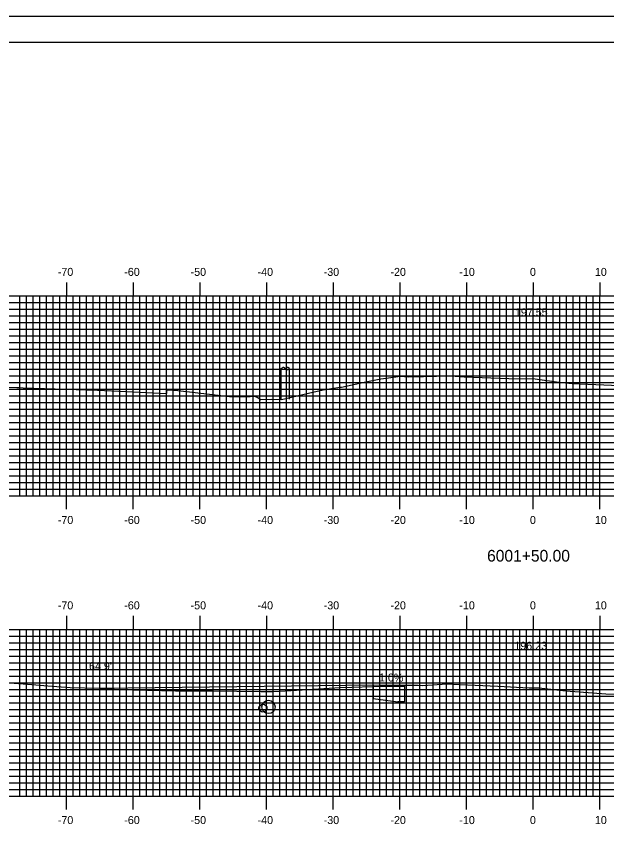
# Model space of a CAD drawing. Extents: x 851300 to 851643, y 366898 to 367118.
# Drawn here: x 851388 to 851476.5, y 366993.9 to 367118.4 of the extents above; entities that cross this region are included whole.
import ezdxf

# ---------------------------------------------------------------- set-up
doc = ezdxf.new("R2010")
doc.units = 0
for name, color, linetype in [('ANNOTATION', 7, 'Continuous'), ('BORDER', 7, 'Continuous'), ('D_Drainage_Culvert', 7, 'Continuous'), ('H_V ANNOTATION', 7, 'Continuous'), ('MAJOR', 7, 'Continuous'), ('MINOR', 7, 'Continuous'), ('PLOT BOUNDARY', 7, 'Continuous'), ('S_Drainage_Invert', 7, 'Continuous'), ('S_Roadway_Centerline', 7, 'Continuous'), ('S_Utilities_Pole_Power', 7, 'Continuous')]:
    doc.layers.add(name, color=color, linetype=linetype)

msp = doc.modelspace()

# ---------------------------------------------------------------- linework, layer by layer
at = {"layer": 'ANNOTATION'}
for p, q in [((851400.61, 367017.65), (851441.5, 367018.16)), ((851441.5, 367018.16), (851441.5, 367016.08)), ((851441.5, 367018.16), (851446.2, 367018.12)), ((851441.5, 367016.08), (851445.2, 367015.62))]:
    msp.add_line(p, q, dxfattribs=at)
for points in [[(851446.2, 367017.87), (851441.5, 367017.91)], [(851446.2, 367018.12), (851446.2, 367015.62), (851445.2, 367015.62)]]:
    msp.add_lwpolyline(points, dxfattribs=at)
at = {"layer": 'BORDER'}
msp.add_lwpolyline([(851315.9, 366904.47), (851635.9, 366904.47), (851635.9, 367114.47), (851315.9, 367114.47)], close=True, dxfattribs=at)
at = {"layer": 'D_Drainage_Culvert'}
msp.add_circle((851425.8, 367014.83), 1, dxfattribs=at)
at = {"layer": 'MAJOR'}
for p, q in [((851395.5, 367078.48), (851395.5, 367076.47)), ((851405.5, 367078.48), (851405.5, 367076.47)), ((851415.5, 367078.48), (851415.5, 367076.47)), ((851425.5, 367078.48), (851425.5, 367076.47)), ((851435.5, 367078.48), (851435.5, 367076.47)), ((851445.5, 367078.48), (851445.5, 367076.47)), ((851455.5, 367078.48), (851455.5, 367076.47)), ((851465.5, 367078.48), (851465.5, 367076.47)), ((851475.5, 367078.48), (851475.5, 367076.47)), ((851325.5, 367076.47), (851605.5, 367076.47)), ((851325.5, 367076.47), (851605.5, 367076.47)), ((851395.5, 367046.47), (851395.5, 367076.47)), ((851405.5, 367046.47), (851405.5, 367076.47)), ((851415.5, 367046.47), (851415.5, 367076.47)), ((851425.5, 367046.47), (851425.5, 367076.47)), ((851435.5, 367046.47), (851435.5, 367076.47)), ((851445.5, 367046.47), (851445.5, 367076.47)), ((851455.5, 367046.47), (851455.5, 367076.47)), ((851465.5, 367046.47), (851465.5, 367076.47)), ((851475.5, 367046.47), (851475.5, 367076.47)), ((851325.5, 367071.47), (851605.5, 367071.47)), ((851325.5, 367066.47), (851605.5, 367066.47)), ((851325.5, 367061.47), (851605.5, 367061.47)), ((851325.5, 367056.47), (851605.5, 367056.47)), ((851325.5, 367051.47), (851605.5, 367051.47)), ((851325.5, 367046.47), (851605.5, 367046.47)), ((851325.5, 367046.47), (851605.5, 367046.47)), ((851395.5, 367044.47), (851395.5, 367046.47)), ((851405.5, 367044.47), (851405.5, 367046.47)), ((851415.5, 367044.47), (851415.5, 367046.47)), ((851425.5, 367044.47), (851425.5, 367046.47)), ((851435.5, 367044.47), (851435.5, 367046.47)), ((851445.5, 367044.47), (851445.5, 367046.47)), ((851455.5, 367044.47), (851455.5, 367046.47)), ((851465.5, 367044.47), (851465.5, 367046.47)), ((851475.5, 367044.47), (851475.5, 367046.47)), ((851395.5, 367028.48), (851395.5, 367026.47)), ((851405.5, 367028.48), (851405.5, 367026.47)), ((851415.5, 367028.48), (851415.5, 367026.47)), ((851425.5, 367028.48), (851425.5, 367026.47)), ((851435.5, 367028.48), (851435.5, 367026.47)), ((851445.5, 367028.48), (851445.5, 367026.47)), ((851455.5, 367028.48), (851455.5, 367026.47)), ((851465.5, 367028.48), (851465.5, 367026.47)), ((851475.5, 367028.48), (851475.5, 367026.47)), ((851325.5, 367026.47), (851605.5, 367026.47)), ((851325.5, 367026.47), (851605.5, 367026.47)), ((851395.5, 367001.47), (851395.5, 367026.47)), ((851405.5, 367001.47), (851405.5, 367026.47)), ((851415.5, 367001.47), (851415.5, 367026.47)), ((851425.5, 367001.47), (851425.5, 367026.47)), ((851435.5, 367001.47), (851435.5, 367026.47)), ((851445.5, 367001.47), (851445.5, 367026.47)), ((851455.5, 367001.47), (851455.5, 367026.47)), ((851465.5, 367001.47), (851465.5, 367026.47)), ((851475.5, 367001.47), (851475.5, 367026.47)), ((851325.5, 367021.47), (851605.5, 367021.47)), ((851325.5, 367016.47), (851605.5, 367016.47)), ((851325.5, 367011.47), (851605.5, 367011.47)), ((851325.5, 367006.47), (851605.5, 367006.47)), ((851325.5, 367001.47), (851605.5, 367001.47)), ((851325.5, 367001.47), (851605.5, 367001.47)), ((851395.5, 366999.47), (851395.5, 367001.47)), ((851405.5, 366999.47), (851405.5, 367001.47)), ((851415.5, 366999.47), (851415.5, 367001.47)), ((851425.5, 366999.47), (851425.5, 367001.47)), ((851435.5, 366999.47), (851435.5, 367001.47)), ((851445.5, 366999.47), (851445.5, 367001.47)), ((851455.5, 366999.47), (851455.5, 367001.47)), ((851465.5, 366999.47), (851465.5, 367001.47)), ((851475.5, 366999.47), (851475.5, 367001.47))]:
    msp.add_line(p, q, dxfattribs=at)
at = {"layer": 'MINOR'}
for p, q in [((851388.5, 367046.47), (851388.5, 367076.47)), ((851389.5, 367046.47), (851389.5, 367076.47)), ((851390.5, 367046.47), (851390.5, 367076.47)), ((851391.5, 367046.47), (851391.5, 367076.47)), ((851392.5, 367046.47), (851392.5, 367076.47)), ((851393.5, 367046.47), (851393.5, 367076.47)), ((851394.5, 367046.47), (851394.5, 367076.47)), ((851396.5, 367046.47), (851396.5, 367076.47)), ((851397.5, 367046.47), (851397.5, 367076.47)), ((851398.5, 367046.47), (851398.5, 367076.47)), ((851399.5, 367046.47), (851399.5, 367076.47)), ((851400.5, 367046.47), (851400.5, 367076.47)), ((851401.5, 367046.47), (851401.5, 367076.47)), ((851402.5, 367046.47), (851402.5, 367076.47)), ((851403.5, 367046.47), (851403.5, 367076.47)), ((851404.5, 367046.47), (851404.5, 367076.47)), ((851406.5, 367046.47), (851406.5, 367076.47)), ((851407.5, 367046.47), (851407.5, 367076.47)), ((851408.5, 367046.47), (851408.5, 367076.47)), ((851409.5, 367046.47), (851409.5, 367076.47)), ((851410.5, 367046.47), (851410.5, 367076.47)), ((851411.5, 367046.47), (851411.5, 367076.47)), ((851412.5, 367046.47), (851412.5, 367076.47)), ((851413.5, 367046.47), (851413.5, 367076.47)), ((851414.5, 367046.47), (851414.5, 367076.47)), ((851416.5, 367046.47), (851416.5, 367076.47)), ((851417.5, 367046.47), (851417.5, 367076.47)), ((851418.5, 367046.47), (851418.5, 367076.47)), ((851419.5, 367046.47), (851419.5, 367076.47)), ((851420.5, 367046.47), (851420.5, 367076.47)), ((851421.5, 367046.47), (851421.5, 367076.47)), ((851422.5, 367046.47), (851422.5, 367076.47)), ((851423.5, 367046.47), (851423.5, 367076.47)), ((851424.5, 367046.47), (851424.5, 367076.47)), ((851426.5, 367046.47), (851426.5, 367076.47)), ((851427.5, 367046.47), (851427.5, 367076.47)), ((851428.5, 367046.47), (851428.5, 367076.47)), ((851429.5, 367046.47), (851429.5, 367076.47)), ((851430.5, 367046.47), (851430.5, 367076.47)), ((851431.5, 367046.47), (851431.5, 367076.47)), ((851432.5, 367046.47), (851432.5, 367076.47)), ((851433.5, 367046.47), (851433.5, 367076.47)), ((851434.5, 367046.47), (851434.5, 367076.47)), ((851436.5, 367046.47), (851436.5, 367076.47)), ((851437.5, 367046.47), (851437.5, 367076.47)), ((851438.5, 367046.47), (851438.5, 367076.47)), ((851439.5, 367046.47), (851439.5, 367076.47)), ((851440.5, 367046.47), (851440.5, 367076.47)), ((851441.5, 367046.47), (851441.5, 367076.47)), ((851442.5, 367046.47), (851442.5, 367076.47)), ((851443.5, 367046.47), (851443.5, 367076.47)), ((851444.5, 367046.47), (851444.5, 367076.47)), ((851446.5, 367046.47), (851446.5, 367076.47)), ((851447.5, 367046.47), (851447.5, 367076.47)), ((851448.5, 367046.47), (851448.5, 367076.47)), ((851449.5, 367046.47), (851449.5, 367076.47)), ((851450.5, 367046.47), (851450.5, 367076.47)), ((851451.5, 367046.47), (851451.5, 367076.47)), ((851452.5, 367046.47), (851452.5, 367076.47)), ((851453.5, 367046.47), (851453.5, 367076.47)), ((851454.5, 367046.47), (851454.5, 367076.47)), ((851456.5, 367046.47), (851456.5, 367076.47)), ((851457.5, 367046.47), (851457.5, 367076.47)), ((851458.5, 367046.47), (851458.5, 367076.47)), ((851459.5, 367046.47), (851459.5, 367076.47)), ((851460.5, 367046.47), (851460.5, 367076.47)), ((851461.5, 367046.47), (851461.5, 367076.47)), ((851462.5, 367046.47), (851462.5, 367076.47)), ((851463.5, 367046.47), (851463.5, 367076.47)), ((851464.5, 367046.47), (851464.5, 367076.47)), ((851466.5, 367046.47), (851466.5, 367076.47)), ((851467.5, 367046.47), (851467.5, 367076.47)), ((851468.5, 367046.47), (851468.5, 367076.47)), ((851469.5, 367046.47), (851469.5, 367076.47)), ((851470.5, 367046.47), (851470.5, 367076.47)), ((851471.5, 367046.47), (851471.5, 367076.47)), ((851472.5, 367046.47), (851472.5, 367076.47)), ((851473.5, 367046.47), (851473.5, 367076.47)), ((851474.5, 367046.47), (851474.5, 367076.47)), ((851325.5, 367075.47), (851605.5, 367075.47)), ((851325.5, 367074.47), (851605.5, 367074.47)), ((851325.5, 367073.47), (851605.5, 367073.47)), ((851325.5, 367072.47), (851605.5, 367072.47)), ((851325.5, 367070.47), (851605.5, 367070.47)), ((851325.5, 367069.47), (851605.5, 367069.47)), ((851325.5, 367068.47), (851605.5, 367068.47)), ((851325.5, 367067.47), (851605.5, 367067.47)), ((851325.5, 367065.47), (851605.5, 367065.47)), ((851325.5, 367064.47), (851605.5, 367064.47)), ((851325.5, 367063.47), (851605.5, 367063.47)), ((851325.5, 367062.47), (851605.5, 367062.47)), ((851325.5, 367060.47), (851605.5, 367060.47)), ((851325.5, 367059.47), (851605.5, 367059.47)), ((851325.5, 367058.47), (851605.5, 367058.47)), ((851325.5, 367057.47), (851605.5, 367057.47)), ((851325.5, 367055.47), (851605.5, 367055.47)), ((851325.5, 367054.47), (851605.5, 367054.47)), ((851325.5, 367053.47), (851605.5, 367053.47)), ((851325.5, 367052.47), (851605.5, 367052.47)), ((851325.5, 367050.47), (851605.5, 367050.47)), ((851325.5, 367049.47), (851605.5, 367049.47)), ((851325.5, 367048.47), (851605.5, 367048.47)), ((851325.5, 367047.47), (851605.5, 367047.47)), ((851325.5, 367025.47), (851605.5, 367025.47)), ((851388.5, 367001.47), (851388.5, 367026.47)), ((851389.5, 367001.47), (851389.5, 367026.47)), ((851390.5, 367001.47), (851390.5, 367026.47)), ((851391.5, 367001.47), (851391.5, 367026.47)), ((851392.5, 367001.47), (851392.5, 367026.47)), ((851393.5, 367001.47), (851393.5, 367026.47)), ((851394.5, 367001.47), (851394.5, 367026.47)), ((851396.5, 367001.47), (851396.5, 367026.47)), ((851397.5, 367001.47), (851397.5, 367026.47)), ((851398.5, 367001.47), (851398.5, 367026.47)), ((851399.5, 367001.47), (851399.5, 367026.47)), ((851400.5, 367001.47), (851400.5, 367026.47)), ((851401.5, 367001.47), (851401.5, 367026.47)), ((851402.5, 367001.47), (851402.5, 367026.47)), ((851403.5, 367001.47), (851403.5, 367026.47)), ((851404.5, 367001.47), (851404.5, 367026.47)), ((851406.5, 367001.47), (851406.5, 367026.47)), ((851407.5, 367001.47), (851407.5, 367026.47)), ((851408.5, 367001.47), (851408.5, 367026.47)), ((851409.5, 367001.47), (851409.5, 367026.47)), ((851410.5, 367001.47), (851410.5, 367026.47)), ((851411.5, 367001.47), (851411.5, 367026.47)), ((851412.5, 367001.47), (851412.5, 367026.47)), ((851413.5, 367001.47), (851413.5, 367026.47)), ((851414.5, 367001.47), (851414.5, 367026.47)), ((851416.5, 367001.47), (851416.5, 367026.47)), ((851417.5, 367001.47), (851417.5, 367026.47)), ((851418.5, 367001.47), (851418.5, 367026.47)), ((851419.5, 367001.47), (851419.5, 367026.47)), ((851420.5, 367001.47), (851420.5, 367026.47)), ((851421.5, 367001.47), (851421.5, 367026.47)), ((851422.5, 367001.47), (851422.5, 367026.47)), ((851423.5, 367001.47), (851423.5, 367026.47)), ((851424.5, 367001.47), (851424.5, 367026.47)), ((851426.5, 367001.47), (851426.5, 367026.47)), ((851427.5, 367001.47), (851427.5, 367026.47)), ((851428.5, 367001.47), (851428.5, 367026.47)), ((851429.5, 367001.47), (851429.5, 367026.47)), ((851430.5, 367001.47), (851430.5, 367026.47)), ((851431.5, 367001.47), (851431.5, 367026.47)), ((851432.5, 367001.47), (851432.5, 367026.47)), ((851433.5, 367001.47), (851433.5, 367026.47)), ((851434.5, 367001.47), (851434.5, 367026.47)), ((851436.5, 367001.47), (851436.5, 367026.47)), ((851437.5, 367001.47), (851437.5, 367026.47)), ((851438.5, 367001.47), (851438.5, 367026.47)), ((851439.5, 367001.47), (851439.5, 367026.47)), ((851440.5, 367001.47), (851440.5, 367026.47)), ((851441.5, 367001.47), (851441.5, 367026.47)), ((851442.5, 367001.47), (851442.5, 367026.47)), ((851443.5, 367001.47), (851443.5, 367026.47)), ((851444.5, 367001.47), (851444.5, 367026.47)), ((851446.5, 367001.47), (851446.5, 367026.47)), ((851447.5, 367001.47), (851447.5, 367026.47)), ((851448.5, 367001.47), (851448.5, 367026.47)), ((851449.5, 367001.47), (851449.5, 367026.47)), ((851450.5, 367001.47), (851450.5, 367026.47)), ((851451.5, 367001.47), (851451.5, 367026.47)), ((851452.5, 367001.47), (851452.5, 367026.47)), ((851453.5, 367001.47), (851453.5, 367026.47)), ((851454.5, 367001.47), (851454.5, 367026.47)), ((851456.5, 367001.47), (851456.5, 367026.47)), ((851457.5, 367001.47), (851457.5, 367026.47)), ((851458.5, 367001.47), (851458.5, 367026.47)), ((851459.5, 367001.47), (851459.5, 367026.47)), ((851460.5, 367001.47), (851460.5, 367026.47)), ((851461.5, 367001.47), (851461.5, 367026.47)), ((851462.5, 367001.47), (851462.5, 367026.47)), ((851463.5, 367001.47), (851463.5, 367026.47)), ((851464.5, 367001.47), (851464.5, 367026.47)), ((851466.5, 367001.47), (851466.5, 367026.47)), ((851467.5, 367001.47), (851467.5, 367026.47)), ((851468.5, 367001.47), (851468.5, 367026.47)), ((851469.5, 367001.47), (851469.5, 367026.47)), ((851470.5, 367001.47), (851470.5, 367026.47)), ((851471.5, 367001.47), (851471.5, 367026.47)), ((851472.5, 367001.47), (851472.5, 367026.47)), ((851473.5, 367001.47), (851473.5, 367026.47)), ((851474.5, 367001.47), (851474.5, 367026.47)), ((851325.5, 367024.47), (851605.5, 367024.47)), ((851325.5, 367023.47), (851605.5, 367023.47)), ((851325.5, 367022.47), (851605.5, 367022.47)), ((851325.5, 367020.47), (851605.5, 367020.47)), ((851325.5, 367019.47), (851605.5, 367019.47)), ((851325.5, 367018.47), (851605.5, 367018.47)), ((851325.5, 367017.47), (851605.5, 367017.47)), ((851325.5, 367015.47), (851605.5, 367015.47)), ((851325.5, 367014.47), (851605.5, 367014.47)), ((851325.5, 367013.47), (851605.5, 367013.47)), ((851325.5, 367012.47), (851605.5, 367012.47)), ((851325.5, 367010.47), (851605.5, 367010.47)), ((851325.5, 367009.47), (851605.5, 367009.47)), ((851325.5, 367008.47), (851605.5, 367008.47)), ((851325.5, 367007.47), (851605.5, 367007.47)), ((851325.5, 367005.47), (851605.5, 367005.47)), ((851325.5, 367004.47), (851605.5, 367004.47)), ((851325.5, 367003.47), (851605.5, 367003.47)), ((851325.5, 367002.47), (851605.5, 367002.47))]:
    msp.add_line(p, q, dxfattribs=at)
at = {"layer": 'PLOT BOUNDARY'}
msp.add_lwpolyline([(851299.72, 366898.35), (851639.72, 366898.35), (851639.72, 367118.35), (851299.72, 367118.35)], close=True, dxfattribs=at)
at = {"layer": 'S_Drainage_Invert'}
msp.add_circle((851424.97, 367014.65), 0.6, dxfattribs=at)
at = {"layer": 'S_Roadway_Centerline'}
for points in [[(851376.55, 367063.17), (851388.04, 367062.74), (851388.46, 367062.73), (851388.98, 367062.71), (851400.14, 367062.32), (851404.41, 367062.13), (851410.52, 367061.86), (851410.53, 367062.38), (851412.21, 367062.29), (851420.41, 367061.36), (851423.07, 367061.39), (851423.65, 367061.44), (851424.1, 367061.28), (851424.63, 367060.95), (851426.3, 367060.99), (851427.74, 367060.95), (851432.45, 367062.03), (851434, 367062.39), (851436.5, 367062.77), (851436.75, 367062.8), (851440.41, 367063.57), (851442.65, 367064.02), (851444.57, 367064.31), (851445.53, 367064.45), (851445.58, 367064.43), (851446.75, 367064.34), (851449.05, 367064.38), (851453.02, 367064.5), (851453.1, 367064.5), (851455.16, 367064.33), (851461.84, 367064.09), (851465.8, 367064.02), (851469.34, 367063.54), (851471.35, 367063.36), (851478.43, 367063.02)], [(851376.34, 367019.26), (851390.28, 367018.21), (851392.7, 367018.02), (851396.06, 367017.75), (851400.39, 367017.67), (851403.39, 367017.44), (851411.85, 367017.27), (851412.64, 367017.26), (851412.95, 367017.23), (851413.35, 367017.25), (851417.35, 367017.23), (851424.68, 367017.16), (851426.48, 367017.16), (851429.19, 367017.29), (851436.56, 367017.74), (851438.28, 367017.81), (851441.45, 367017.9), (851445.77, 367018.12), (851448.27, 367018.08), (851448.88, 367018.05), (851451.85, 367018.23), (851452.25, 367018.32), (851460.2, 367017.96), (851464.88, 367017.7), (851466.33, 367017.71), (851470.39, 367017.27), (851476.38, 367016.79), (851478.76, 367016.74)]]:
    msp.add_lwpolyline(points, dxfattribs=at)
at = {"layer": 'S_Utilities_Pole_Power'}
for p, q in [((851427.71, 367065.59), (851427.87, 367065.7)), ((851427.71, 367060.97), (851427.71, 367065.59)), ((851428.18, 367065.7), (851428.34, 367065.59)), ((851428.49, 367065.7), (851428.34, 367065.59)), ((851428.34, 367065.59), (851428.49, 367065.48)), ((851428.96, 367065.59), (851428.81, 367065.7)), ((851428.81, 367065.48), (851428.96, 367065.59)), ((851428.96, 367060.97), (851428.96, 367065.59))]:
    msp.add_line(p, q, dxfattribs=at)
for centre, start, end in [((851428.03, 367065.48), 90, 125.2644), ((851428.03, 367065.48), 54.7356, 90), ((851428.65, 367065.48), 90, 125.2644), ((851428.65, 367065.7), 234.7356, 270), ((851428.65, 367065.48), 54.7356, 90), ((851428.65, 367065.7), 270, 305.2644)]:
    msp.add_arc(centre, 0.271, start, end, dxfattribs=at)

# ---------------------------------------------------------------- texts
at = {"layer": 'ANNOTATION'}
msp.add_text("64.9'", height=1.2, dxfattribs=at).set_placement((851398.87, 367020.36))
msp.add_text('1.0%', height=1.2, rotation=359.4271, dxfattribs=at).set_placement((851442.37, 367018.66))
at = {"layer": 'H_V ANNOTATION'}
for s, height, p in [('-70', 1.2, (851394.19, 367079.47)), ('-60', 1.2, (851404.16, 367079.47)), ('-50', 1.2, (851414.11, 367079.47)), ('-40', 1.2, (851424.16, 367079.47)), ('-30', 1.2, (851434.08, 367079.47)), ('-20', 1.2, (851444.09, 367079.47)), ('-10', 1.2, (851454.43, 367079.47)), ('0', 1.2, (851465.02, 367079.47)), ('10', 1.2, (851474.76, 367079.47)), ('197.55', 1.2, (851462.77, 367073.41)), ('-70', 1.2, (851394.19, 367042.27)), ('-60', 1.2, (851404.16, 367042.27)), ('-50', 1.2, (851414.11, 367042.27)), ('-40', 1.2, (851424.16, 367042.27)), ('-30', 1.2, (851434.08, 367042.27)), ('-20', 1.2, (851444.09, 367042.27)), ('-10', 1.2, (851454.43, 367042.27)), ('0', 1.2, (851465.02, 367042.27)), ('10', 1.2, (851474.76, 367042.27)), ('6001+50.00', 1.75, (851458.59, 367036.63)), ('-70', 1.2, (851394.19, 367029.47)), ('-60', 1.2, (851404.16, 367029.47)), ('-50', 1.2, (851414.11, 367029.47)), ('-40', 1.2, (851424.16, 367029.47)), ('-30', 1.2, (851434.08, 367029.47)), ('-20', 1.2, (851444.09, 367029.47)), ('-10', 1.2, (851454.43, 367029.47)), ('0', 1.2, (851465.02, 367029.47)), ('10', 1.2, (851474.76, 367029.47)), ('196.23', 1.2, (851462.68, 367023.41)), ('-70', 1.2, (851394.19, 366997.27)), ('-60', 1.2, (851404.16, 366997.27)), ('-50', 1.2, (851414.11, 366997.27)), ('-40', 1.2, (851424.16, 366997.27)), ('-30', 1.2, (851434.08, 366997.27)), ('-20', 1.2, (851444.09, 366997.27)), ('-10', 1.2, (851454.43, 366997.27)), ('0', 1.2, (851465.02, 366997.27)), ('10', 1.2, (851474.76, 366997.27))]:
    msp.add_text(s, height=height, dxfattribs=at).set_placement(p)
at = {"layer": 'S_Roadway_Centerline'}
for s, p in [('C', (851465.8, 367064.02)), ('L', (851465.8, 367064.01)), ('C', (851465.8, 367064.02)), ('L', (851465.8, 367064.01)), ('C', (851466.32, 367017.71)), ('C', (851466.32, 367017.71)), ('L', (851466.33, 367017.7)), ('L', (851466.33, 367017.7))]:
    msp.add_text(s, height=0.0146, dxfattribs=at).set_placement(p)

doc.saveas('drawing.dxf')
